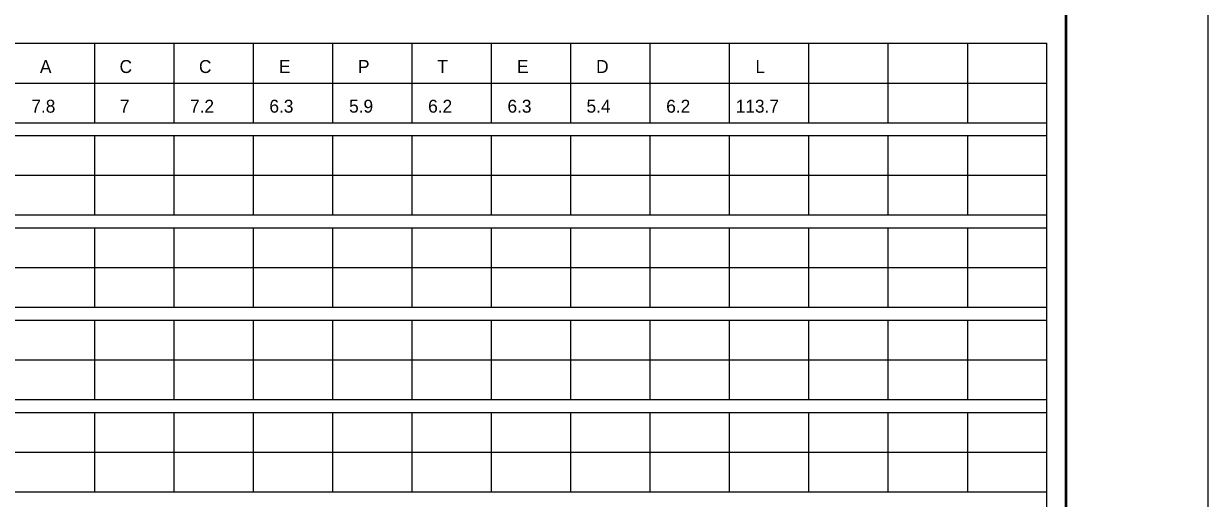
# Model space of a CAD drawing. Extents: x 17890459 to 17890580, y 17897938 to 17898017.
# Drawn here: x 17890546.34 to 17890580.04, y 17897978.61 to 17897992.09 of the extents above; entities that cross this region are included whole.
import ezdxf

# ---------------------------------------------------------------- set-up
doc = ezdxf.new("R2010")
doc.units = 0
for name, color, linetype in [('GSSign', 7, 'Continuous'), ('PlotBorder_dp', 7, 'Continuous'), ('SheetBorder_dp', 7, 'Continuous'), ('SheetLinesMisc2_dp', 7, 'Continuous')]:
    doc.layers.add(name, color=color, linetype=linetype)

msp = doc.modelspace()

# ---------------------------------------------------------------- linework, layer by layer
at = {"layer": 'PlotBorder_dp'}
msp.add_lwpolyline([(17890458.908, 17897939.544), (17890580.045, 17897939.544), (17890580.045, 17898017.365), (17890458.908, 17898017.365)], close=True, dxfattribs=at)
at = {"layer": 'SheetBorder_dp'}
msp.add_line((17890576.007, 17898016.631), (17890576.007, 17897940.278), dxfattribs=at)
at = {"layer": 'SheetLinesMisc2_dp'}
for p, q in [((17890575.98, 17897946.221), (17890575.98, 17898016.456)), ((17890519.957, 17897991.536), (17890575.447, 17897991.536)), ((17890548.359, 17897991.536), (17890548.359, 17897989.281)), ((17890550.617, 17897991.536), (17890550.617, 17897989.281)), ((17890552.874, 17897991.536), (17890552.874, 17897989.281)), ((17890555.132, 17897991.536), (17890555.132, 17897989.281)), ((17890557.388, 17897991.536), (17890557.388, 17897989.281)), ((17890559.646, 17897991.536), (17890559.646, 17897989.281)), ((17890561.903, 17897991.536), (17890561.903, 17897989.281)), ((17890564.161, 17897991.536), (17890564.161, 17897989.281)), ((17890566.418, 17897991.536), (17890566.418, 17897989.281)), ((17890568.675, 17897991.536), (17890568.675, 17897989.281)), ((17890570.932, 17897991.536), (17890570.932, 17897989.281)), ((17890573.19, 17897991.536), (17890573.19, 17897989.281)), ((17890575.447, 17897947.331), (17890575.447, 17897991.536)), ((17890519.957, 17897990.408), (17890575.447, 17897990.408)), ((17890519.957, 17897989.281), (17890575.447, 17897989.281)), ((17890519.957, 17897988.914), (17890575.447, 17897988.914)), ((17890548.359, 17897988.914), (17890548.359, 17897986.659)), ((17890550.617, 17897988.914), (17890550.617, 17897986.659)), ((17890552.874, 17897988.914), (17890552.874, 17897986.659)), ((17890555.132, 17897988.914), (17890555.132, 17897986.659)), ((17890557.388, 17897988.914), (17890557.388, 17897986.659)), ((17890559.646, 17897988.914), (17890559.646, 17897986.659)), ((17890561.903, 17897988.914), (17890561.903, 17897986.659)), ((17890564.161, 17897988.914), (17890564.161, 17897986.659)), ((17890566.418, 17897988.914), (17890566.418, 17897986.659)), ((17890568.675, 17897988.914), (17890568.675, 17897986.659)), ((17890570.932, 17897988.914), (17890570.932, 17897986.659)), ((17890573.19, 17897988.914), (17890573.19, 17897986.659)), ((17890519.957, 17897987.786), (17890575.447, 17897987.786)), ((17890519.957, 17897986.659), (17890575.447, 17897986.659)), ((17890519.957, 17897986.291), (17890575.447, 17897986.291)), ((17890548.359, 17897986.291), (17890548.359, 17897984.037)), ((17890550.617, 17897986.291), (17890550.617, 17897984.037)), ((17890552.874, 17897986.291), (17890552.874, 17897984.037)), ((17890555.132, 17897986.291), (17890555.132, 17897984.037)), ((17890557.388, 17897986.291), (17890557.388, 17897984.037)), ((17890559.646, 17897986.291), (17890559.646, 17897984.037)), ((17890561.903, 17897986.291), (17890561.903, 17897984.037)), ((17890564.161, 17897986.291), (17890564.161, 17897984.037)), ((17890566.418, 17897986.291), (17890566.418, 17897984.037)), ((17890568.675, 17897986.291), (17890568.675, 17897984.037)), ((17890570.932, 17897986.291), (17890570.932, 17897984.037)), ((17890573.19, 17897986.291), (17890573.19, 17897984.037)), ((17890519.957, 17897985.165), (17890575.447, 17897985.165)), ((17890519.957, 17897984.037), (17890575.447, 17897984.037)), ((17890519.957, 17897983.669), (17890575.447, 17897983.669)), ((17890548.359, 17897983.669), (17890548.359, 17897981.415)), ((17890550.617, 17897983.669), (17890550.617, 17897981.415)), ((17890552.874, 17897983.669), (17890552.874, 17897981.415)), ((17890555.132, 17897983.669), (17890555.132, 17897981.415)), ((17890557.388, 17897983.669), (17890557.388, 17897981.415)), ((17890559.646, 17897983.669), (17890559.646, 17897981.415)), ((17890561.903, 17897983.669), (17890561.903, 17897981.415)), ((17890564.161, 17897983.669), (17890564.161, 17897981.415)), ((17890566.418, 17897983.669), (17890566.418, 17897981.415)), ((17890568.675, 17897983.669), (17890568.675, 17897981.415)), ((17890570.932, 17897983.669), (17890570.932, 17897981.415)), ((17890573.19, 17897983.669), (17890573.19, 17897981.415)), ((17890519.957, 17897982.543), (17890575.447, 17897982.543)), ((17890519.957, 17897981.415), (17890575.447, 17897981.415)), ((17890519.957, 17897981.048), (17890575.447, 17897981.048)), ((17890548.359, 17897981.048), (17890548.359, 17897978.794)), ((17890550.617, 17897981.048), (17890550.617, 17897978.794)), ((17890552.874, 17897981.048), (17890552.874, 17897978.794)), ((17890555.132, 17897981.048), (17890555.132, 17897978.794)), ((17890557.388, 17897981.048), (17890557.388, 17897978.794)), ((17890559.646, 17897981.048), (17890559.646, 17897978.794)), ((17890561.903, 17897981.048), (17890561.903, 17897978.794)), ((17890564.161, 17897981.048), (17890564.161, 17897978.794)), ((17890566.418, 17897981.048), (17890566.418, 17897978.794)), ((17890568.675, 17897981.048), (17890568.675, 17897978.794)), ((17890570.932, 17897981.048), (17890570.932, 17897978.794)), ((17890573.19, 17897981.048), (17890573.19, 17897978.794)), ((17890519.957, 17897979.92), (17890575.447, 17897979.921)), ((17890519.957, 17897978.794), (17890575.447, 17897978.794))]:
    msp.add_line(p, q, dxfattribs=at)

# ---------------------------------------------------------------- texts
at = {"layer": 'GSSign'}
for s, height, p in [('A', 0.368, (17890546.806, 17897990.692)), ('C', 0.368, (17890549.072, 17897990.692)), ('C', 0.368, (17890551.33, 17897990.692)), ('E', 0.368, (17890553.605, 17897990.692)), ('P', 0.368, (17890555.854, 17897990.692)), ('T', 0.368, (17890558.112, 17897990.692)), ('E', 0.368, (17890560.379, 17897990.692)), ('D', 0.368, (17890562.628, 17897990.692)), ('L', 0.368, (17890567.161, 17897990.692)), ('7.8', 0.3676, (17890546.561, 17897989.565)), ('7', 0.368, (17890549.081, 17897989.565)), ('7.2', 0.3676, (17890551.076, 17897989.565)), ('6.3', 0.3676, (17890553.334, 17897989.565)), ('5.9', 0.3676, (17890555.601, 17897989.565)), ('6.2', 0.3676, (17890557.85, 17897989.565)), ('6.3', 0.3676, (17890560.107, 17897989.565)), ('5.4', 0.3676, (17890562.356, 17897989.565)), ('6.2', 0.3676, (17890564.623, 17897989.565)), ('113.7', 0.3676, (17890566.601, 17897989.565))]:
    msp.add_text(s, height=height, dxfattribs=at).set_placement(p)

doc.saveas('drawing.dxf')
